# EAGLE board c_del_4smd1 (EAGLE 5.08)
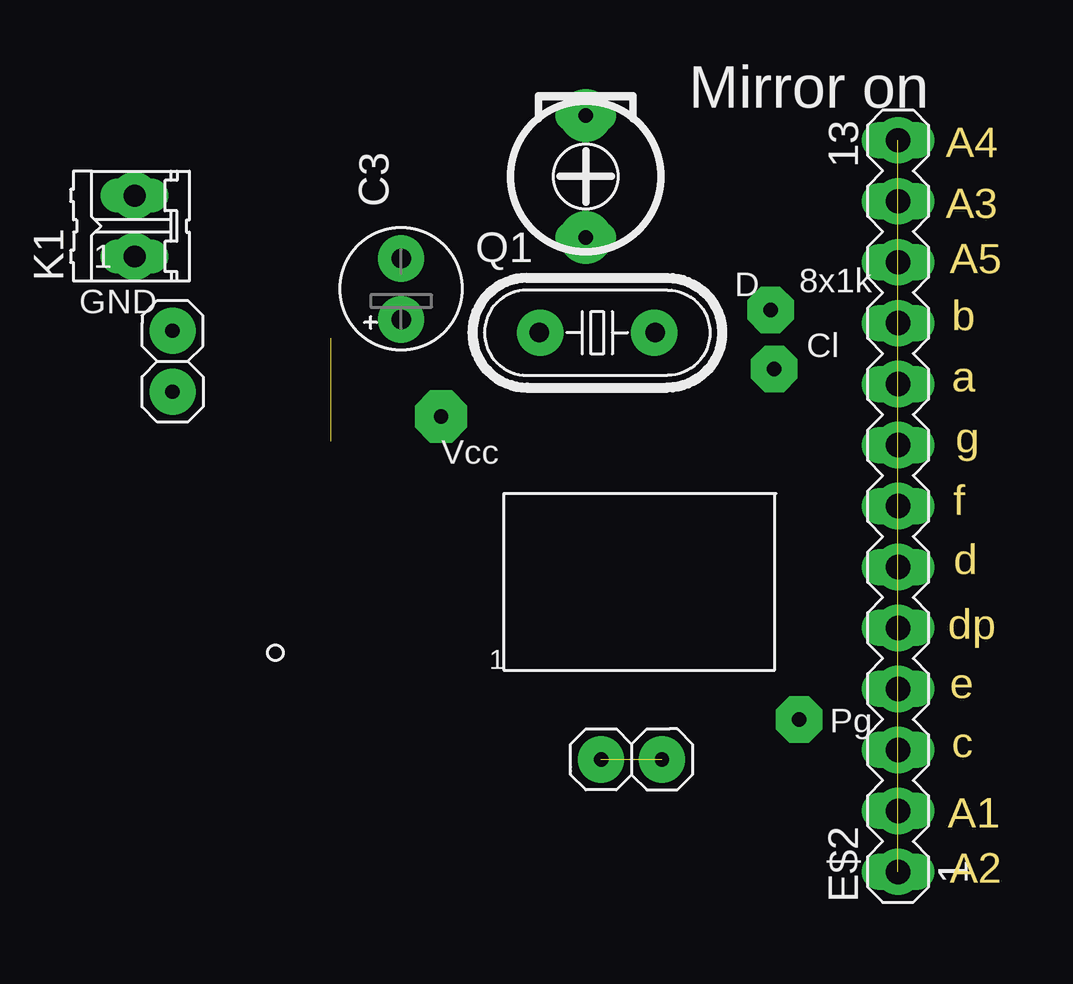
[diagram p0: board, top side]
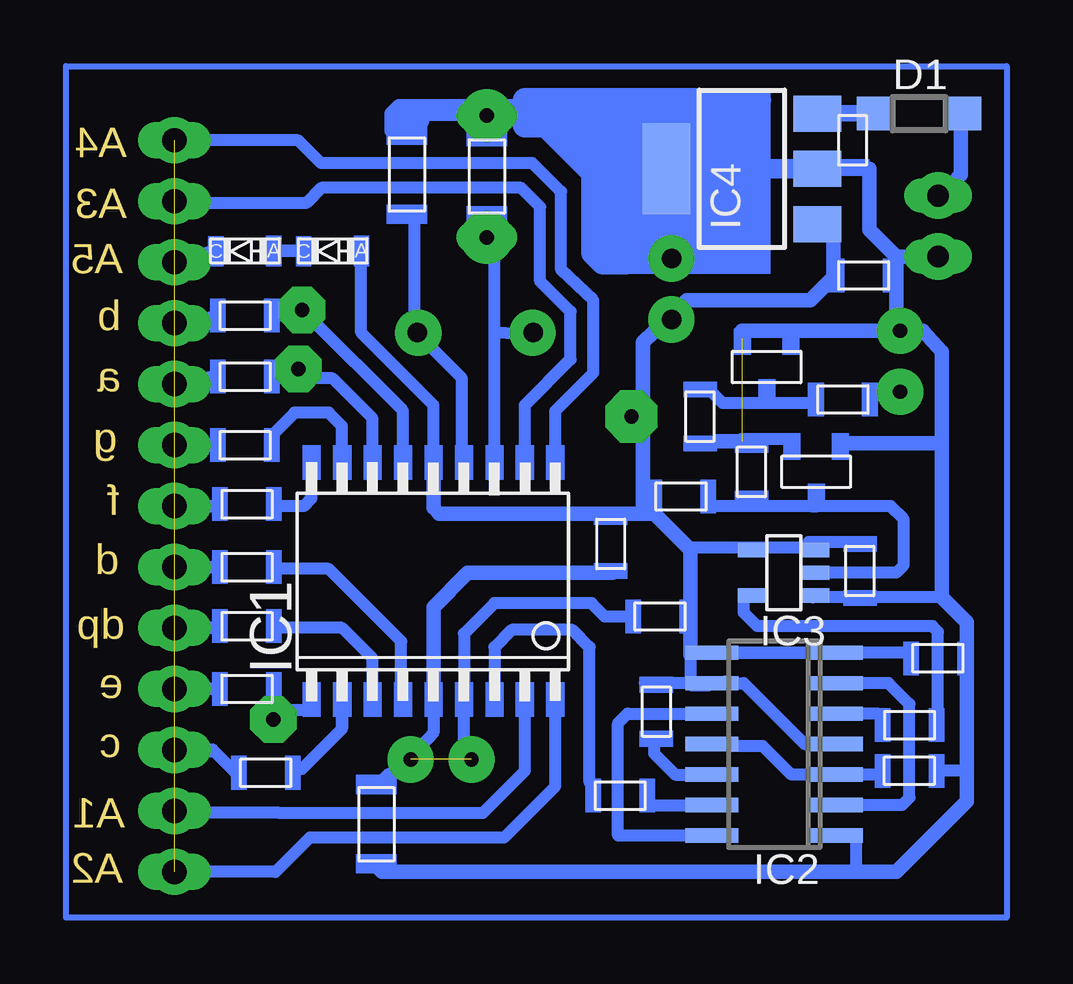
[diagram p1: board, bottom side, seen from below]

No outline drawn. Coordinates in mm, seen from the top.
Copper layers (1*16): Top 0.035mm / dielectric 1.5mm / Bottom 0.035mm
Design rules "default": minimum track width 10mil, minimum drill 24mil, track to track 8mil, track to pad 8mil, pad to pad 8mil, via to via 8mil, smd to smd 8mil, copper to edge 40mil, drill to drill 8mil, minimum pad ring 10mil, minimum via ring 8mil, stop-mask expansion 0mil, vias tented up to drill 0mil, thermal gap 10mil

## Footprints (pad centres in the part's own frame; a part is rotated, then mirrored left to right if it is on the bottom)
E2,5-5 = drill 0.813 pad 1.6 round: + -1.27,0 | drill 0.813 pad 1.6 octagon: - 1.27,0
SOD123 = smd 1.4 x 1.4: A 1.9,0; C -1.9,0
MA13-1 = drill 1.016 long: 1 -15.24,0; 2 -12.7,0; 3 -10.16,0; 4 -7.62,0; 5 -5.08,0; 6 -2.54,0; 7 0,0; 8 2.54,0; 9 5.08,0; 10 7.62,0; 11 10.16,0; 12 12.7,0; 13 15.24,0
C_TRIM = drill 0.6 pad 1.27 long: P$1 0,2.54; P$2 0,-2.54 | drill 0.6 pad 1.778 round: P$3 0,2.54; P$4 0,-2.54
MA02_1,7 = drill 0.6 pad 1.778 round: P$1 -1.27,0; P$2 1.27,0
SO-14R = smd 0.6 x 2.2 bottom: 1 -3.81,-2.6; 2 -2.54,-2.6; 3 -1.27,-2.6; 4 0,-2.6; 5 1.27,-2.6; 6 2.54,-2.6; 7 3.81,-2.6; 8 3.81,2.6; 9 2.54,2.6; 10 1.27,2.6; 11 0,2.6; 12 -1.27,2.6; 13 -2.54,2.6; 14 -3.81,2.6
SOT23-5 = smd 0.6 x 1.2: 1 -0.95,-1.306; 2 0,-1.306; 3 0.95,-1.306; 4 0.95,1.306; 5 -0.95,1.306
SOT223 = smd 1.5 x 2: 1 -2.3,-3.15; 2 0,-3.15; 3 2.3,-3.15 | smd 3.8 x 2: 4 0,3.15
02P = drill 0.914 long: 1 -1.27,0; 2 1.27,0
HC49U-V = drill 0.813 octagon: 1 -2.413,0; 2 2.413,0

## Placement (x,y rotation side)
C3  47uF  [E2,5-5]  13.97,26.19 90 top
D1  Sh-d  [SOD123]  3.65,33.5 0 bottom
D2  [D-805]  28.1,27.78 0 bottom
D3  [D-805]  31.75,27.78 0 bottom
D4-5  BAV70  [SOT23A]  10,22.94 180 bottom
E$2  [MA13-1]  34.69,17.15 90 top
E$3  10p  [C1206A]  21.67,30.88 270 bottom
E$4  5-25p  [C_TRIM]  21.67,30.88 0 top
E$5  1k  [C0805A]  31.75,25.08 0 bottom
E$7  680R  [C0805A]  13.57,17.54 180 bottom
E$8  100n  [C0805A]  6.11,14.45 270 bottom
E$10  [MA02_1,7]  23.57,6.59 0 top
E$12  1k  [C0805A]  31.75,22.54 0 bottom
E$13  1k  [C0805A]  31.75,19.68 0 bottom
E$14  1k  [C0805A]  31.67,17.22 0 bottom
E$15  1k  [C0805A]  31.67,14.61 0 bottom
E$16  1k  [C0805A]  31.67,12.14 0 bottom
E$17  1k  [C0805A]  31.67,9.53 0 bottom
E$18  1k  [C0805A]  30.88,6.03 180 bottom
E$23  10k  [C0805A]  14.45,12.54 180 bottom
E$25  0R0  [C1206A]  26.27,3.89 270 bottom
E$26  470R  [C0805A]  4.05,6.11 180 bottom
E$28  100n  [C0805A]  2.86,10.8 180 bottom
E$30  47k  [C0805A]  10.64,18.57 270 bottom
E$31  100n  [C0805A]  6.43,32.39 90 bottom
E$32  100n  [C0805A]  5.95,26.75 180 bottom
E$33  4u7  [C0805A]  6.83,21.59 0 bottom
E$34  0R0  [C0805A]  4.05,8.02 0 bottom
E$35  100n  [C0805A]  16.51,15.56 90 bottom
E$39  18p  [C1206A]  25,30.96 270 bottom
E$40  0R0  [C0805A]  14.61,8.57 90 bottom
E$41  0R0  [C0805A]  16.11,5.08 0 bottom
E$42  [MA02_1,7]  4.45,23.18 90 top
E$43  4u7  [C0805A]  12.78,20.88 270 bottom
IC1  F628A  [SO-18W_R]  23.89,14.05 0 top
IC2  ACT74  [SO-14R]  9.68,7.22 270 top
IC3  xHC123  [SOT23-5]  9.29,14.37 90 bottom
IC4  78M05  [SOT223]  11.03,31.19 90 bottom
K1  [02P]  2.86,28.81 90 top
Q1  20MHz  [HC49U-V]  22.15,24.37 0 top
T1  HF-N  [SOT23A]  7.94,18.57 180 bottom

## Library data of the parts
C3 = rcl
D1-D3 = diode1
D4-5 T1 = transistor-npn1
E$2 = con-lstb
E$3 E$5 E$7 E$8 E$12-E$18 E$23 E$25 E$26 E$28 E$30-E$35 E$39-E$41 E$43 = rcl_upr
E$4 = con-moje
E$10 E$42 = con-lstb1
IC1 IC2 = microchip
IC3 = burr-brown
IC4 = v-reg
K1 = con-amp-quick
Q1 = crystal

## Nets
S$4: E$2.3
S$9: E$2.4
S$11: E$10.P$1
S$13: E$2.5
S$14: E$2.6
S$15: E$2.7
S$18: E$2.8
S$20: E$2.9
S$21: E$2.10
S$33: E$2.11

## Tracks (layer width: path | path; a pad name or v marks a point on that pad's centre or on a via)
KON1  (via drill 0.6 pad 1.93)
  other vias: 13.97,24.92 2.86,30.08 2.86,27.54
S$1
  Bottom 0.5: 26.99,31.43 28.57,31.43 29.53,32.38 34.69,32.38
S$2
  Bottom 0.5: 24.84,6.67 23.89,7.7 23.89,9.05 23.89,10.64
  Bottom 0.61: 23.89,9.05 23.89,12.94 22.46,14.37 16.43,14.37
S$3  (via drill 0.6 pad 2.18)
  other vias: 15.64,20.88
S$4
  Bottom 0.53: 33.1,6.99 E$2.3
S$5  (via drill 0.6 pad 1.93)
  other vias: 29.37,25.32
S$6
  Bottom 0.53: 29.53,27.78 30.4,27.78
S$7
  Bottom 0.406: 6.43,8.49 6.35,8.49
S$8
  Bottom 0.5: 5.4,8.49 6.67,8.49
S$9
  Bottom 0.53: 33.1,9.53 E$2.4
S$10
  Bottom 0.5: 6.43,9.76 4.92,9.76 4.05,8.89 4.05,5 4.37,4.68 6.59,4.68
S$11
  Bottom 0.5: E$10.P$1 22.62,6.91 22.62,9.05
S$12
  Bottom 0.5: 29.05,18.89 28.97,18.81 28.97,17.46 29.29,17.14 30.56,17.14
S$13
  Bottom 0.53: 33.1,12.06 E$2.5
S$14
  Bottom 0.53: E$2.6 33.18,14.61
S$15
  Bottom 0.53: 33.02,17.14 E$2.7
S$16
  Bottom 0.5: 27.7,19.29 27.7,20.48 28.26,21.03 29.69,21.03 30.64,20.08 30.64,19.53
  Bottom 0.61: 30.64,19.53 30.64,19.84
S$17
  Bottom 0.5: 27.7,9.37 27.7,7.86
S$18
  Bottom 0.53: 33.1,19.68 E$2.8
S$19
  Bottom 0.5: 23.89,19.37 23.89,21.35 26.91,24.37 26.91,27.7
S$20
  Bottom 0.53: 33.1,22.54 E$2.9
S$21
  Bottom 0.53: 33.1,25 E$2.10
S$22
  Bottom 0.5: 22.7,19.29 22.7,22.46 24.69,24.45 24.69,29.45
S$23
  Bottom 0.5: 26.43,18.89 26.43,20.8 28.1,22.46 30.56,22.46
S$24
  Bottom 0.5: 26.43,9.45 26.43,10.79 27.7,12.06 30.4,12.06
S$25
  Bottom 0.5: 30.56,9.6 30.48,9.53 30.48,8.97 30.16,8.65 28.89,8.65
S$26  (1 unrouted)
  Bottom 0.61: 11.03,19.84 12.06,19.84
S$27
  Bottom 0.5: 12.94,8.49 15.8,8.49 16.19,8.1 16.19,3.41 12.86,3.41
S$28
  Bottom 0.5: 22.15,3.33 20.95,3.33 18.81,5.48 18.81,8.97
S$29
  Bottom 0.5: 25.16,19.29 25.16,21.11 29.13,25.08 30.48,25.08
S$30
  Bottom 0.406: 6.59,11.03 6.67,11.11 9.21,11.03 12.46,11.11
S$31  (via drill 0.6 pad 1.93)
  other vias: 29.53,22.86
S$32
  Bottom 0.5: 19.84,24.29 21.19,24.37
S$33
  Bottom 0.53: 33.1,27.78 E$2.11
S$34
  Bottom 0.61: 15.16,23.97 13.34,25.72 8.18,25.72 7.22,26.67 7.22,28.65
S$35
  Bottom 0.5: 25.16,9.21 25.24,9.29 25.24,11.51 28.26,14.53 30.48,14.53
S$36
  Bottom 0.5: 21.35,18.97 21.35,28.26
S$37
  Bottom 0.61: 16.35,33.5 25.56,33.5
S$38
  Bottom 0.5: 21.83,4.37 23.57,4.37 30.32,4.37 34.85,4.37
S$39  (via drill 0.6 pad 1.93)
  other vias: 30.56,8.26
S$40
  Bottom 0.5: 20.08,19.37 20.08,21.35 18.18,23.26 18.18,25.24 19.45,26.51 19.45,29.61 20.24,30.4 28.57,30.4 29.21,29.77 34.85,29.77
S$41
  Bottom 0.5: 11.59,7.14 10.16,7.14 8.97,5.95 7.62,5.95
S$42
  Bottom 0.5: 29.84,6.03 29.69,6.19 29.37,6.19 27.7,7.86 27.7,8.97
S$43
  Bottom 0.5: 29.05,3.33 | 29.05,3.33 30.48,1.91 34.69,1.91 | 20.95,3.33 29.05,3.33
S$44
  Bottom 0.5: 21.75,4.45 20.08,6.11 20.08,8.81
S$45
  Bottom 0.5: 9.05,19.92 11.11,19.92
S$46
  Bottom 0.5: 32.15,6.03 33.02,6.91 34.29,6.91
S$47
  Bottom 0.5: 14.92,4.68 13.26,4.68
S$48
  Bottom 0.5: 13.02,5.95 13.81,5.95 14.68,6.83 14.68,7.3
S$49
  Bottom 0.5: 4.37,21.83 5.79,21.83
S$50
  Bottom 0.5: 12.7,9.76 15.08,9.76
S$51
  Bottom 0.25: 0,0 39.21,0 39.21,35.48 0,35.48 0,0
S$52  (via drill 0.6 pad 2.18)
  other vias: 21.67,28.34
S$53
  Bottom 0.5: 11.67,9.76 11.75,9.84
S$54
  Bottom 0.5: 18.81,19.37 18.81,21.11 17.22,22.7 17.22,25.72 18.57,26.99 18.57,30.24 19.76,31.43 28.57,31.43
S$55  (via drill 0.6 pad 1.93)
  other vias: 13.97,27.46
S$56
  Bottom 1.016: 15.88,27.3 16.83,27.3 17.22,27.7 17.22,31.04 19.13,32.94 19.13,33.97 17.07,33.97 | 17.07,33.97 14.53,33.97 15.32,33.18 18.49,33.18 17.22,31.91 16.75,31.91 17.22,32.38 17.22,33.02 20.08,33.02 20.08,33.89 | 17.14,34.05 17.07,33.97 | 17.14,34.05 20.08,34.05 | 10.32,34.05 17.14,34.05
S$57
  Bottom 0.5: 8.02,21.43 10.64,21.43
S$58
  Bottom 0.61: 2.06,29.92 2.06,30.8 1.91,30.96 1.91,33.34
S$59  (via drill 0.6 pad 2.18)
  other vias: 21.67,33.42
S$61  (via drill 0.6 pad 1.93)  (1 unrouted)
  other vias: 22.3,6.59 24.84,6.59 4.45,21.91 4.45,24.45
S$62
  Bottom 0.5: 7.54,7.22 8.41,7.22 10.95,9.76 12.3,9.76 12.38,9.68 13.18,9.68 13.18,10.95 | 3.97,11.03 7.14,11.03
  Bottom 0.53: 6.35,11.03 7.14,11.03 13.18,11.03 | 13.18,11.03 13.18,10.95 | 13.18,11.03 13.18,12.94
  Bottom 0.61: 23.89,18.89 23.89,17.07 23.65,16.83 15.16,16.83 | 15.16,16.83 14.68,16.83 13.18,15.32 13.18,10.95 | 15.16,16.83 15.16,23.97
S$63
  Bottom 0.61: 16.91,33.81 25.32,33.81 25.64,33.5 25.64,33.18
S$64  (via drill 0.6 pad 1.93)
  other vias: 24.53,24.37
S$65
  Bottom 0.61: 7.7,31.11 7.78,31.2 8.18,30.96
  Bottom 0.813: 7.78,31.2 13.49,31.2
S$66  (via drill 0.6 pad 1.93)
  other vias: 19.76,24.37
S$69  (via drill 0.6 pad 1.93)  (12 unrouted)
  other vias: 34.69,32.38 34.69,29.84 34.69,27.3 34.69,24.77 34.69,22.23 34.69,19.69 34.69,17.15 34.69,14.61 34.69,12.07 34.69,9.53 34.69,6.99 34.69,4.45 34.69,1.91
S$70
  Bottom 0.5: 21.35,9.53 21.35,11.27 20.64,11.99 18.1,11.99 17.38,11.27 17.38,5.64 17.3,5.56
S$71
  Bottom 0.5: 22.62,9.21 22.62,11.83 21.35,13.1 17.3,13.1 16.75,12.54 15.48,12.54
S$72
  Bottom 0.5: 5.32,5.95 6.11,5.95
S$73
  Bottom 0.5: 1.83,6.11 2.78,6.11
S$74
  Bottom 0.5: 10.95,13.41 10.95,12.7 10.4,12.14 3.1,12.14 2.86,11.91 2.86,8.57
S$75
  Bottom 0.5: 7.62,15.4 13.18,15.4
S$78
  Bottom 0.5: 26.19,5.56 25.8,5.95 25.24,6.27
S$79
  Bottom 0.5: 11.03,24.45 11.11,24.45 | 6.27,1.91 6.27,3.41 | 2.7,13.34 8.1,13.34
  Bottom 0.61: 4.6,24.45 11.03,24.45 | 4.6,24.45 4.6,27.46 | 4.37,24.45 4.29,24.37 | 4.37,24.45 4.6,24.45 | 4.37,24.45 3.49,24.45 2.7,23.57 2.7,19.76 | 2.7,19.76 6.91,19.76 | 26.27,2.14 26.04,1.91 6.27,1.91 4.6,1.91 1.67,4.84 1.67,12.3 2.7,13.34 2.7,19.76
S$81
  Bottom 0.61: 2.78,27.54 4.6,27.54 5.71,28.65 5.71,31.19 6.83,31.19
S$83
  Bottom 0.406: 35,29.84 34.69,29.84
S$85
  Bottom 0.5: 5.87,15.64 8.26,15.64 8.26,15.4
S$87
  Bottom 0.5: 8.18,17.14 7.86,17.14 | 8.18,17.14 4.84,17.14 4.29,16.59 4.29,14.68 4.6,14.37 7.7,14.37 | 8.18,17.14 12.22,17.14 12.46,17.3 12.46,17.94 | 11.83,21.43 12.38,21.99 | 9.92,21.43 11.75,21.43 | 15.16,20.8 15.72,20.8
S$102
  Bottom 0.61: 24.37,33.18 25.56,33.18
S$103
  Bottom 0.61: 25.64,32.78 25.64,33.34
(copper drawn outside any net)
  shapes: Bottom area x1

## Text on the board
Dimension: A4 | A3 | A5 | b | a | g | f | d | dp | e | c | A1 | A2
tPlace: Mirror on | D | 8x1k | GND | Cl | Vcc | Pg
